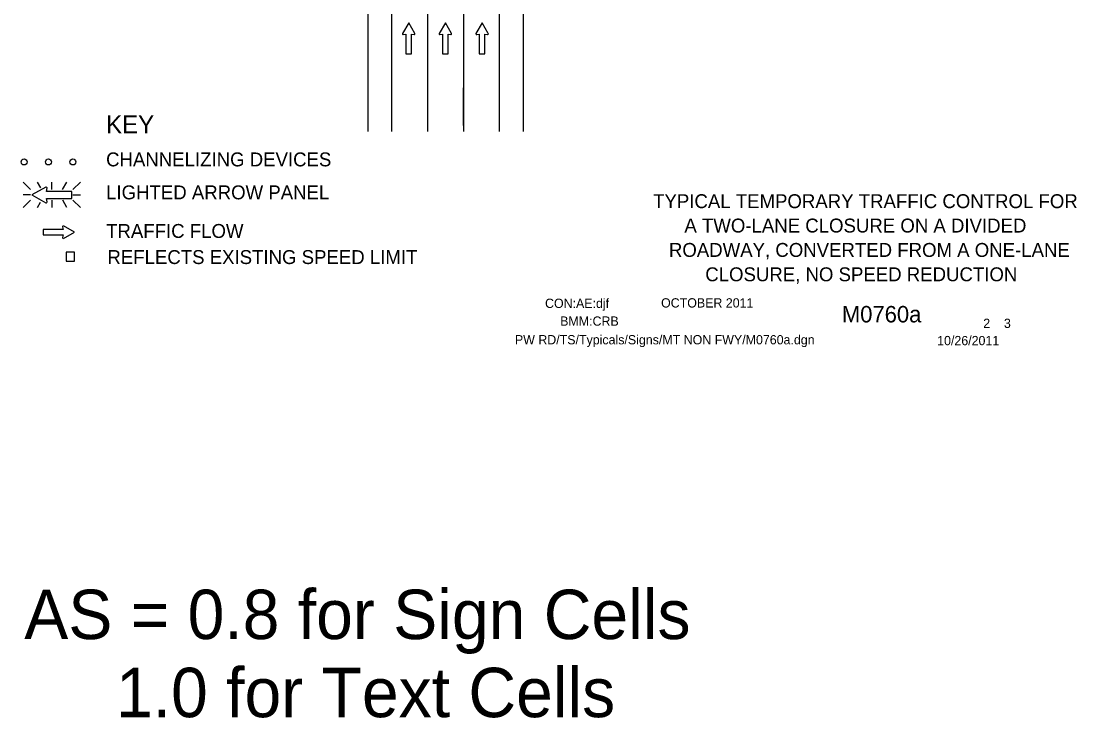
# Model space of a CAD drawing. Extents: x 16735 to 19504, y 6970 to 8243.
# Drawn here: x 17769 to 18475, y 6970 to 7436 of the extents above; entities that cross this region are included whole.
import ezdxf

# ---------------------------------------------------------------- set-up
doc = ezdxf.new("R2010")
doc.units = 0
for name, color, linetype in [('ALI_LEGAL_EX', 7, 'Continuous'), ('BORDER', 7, 'Continuous'), ('BORDER_SIGNAL_WO', 7, 'Continuous'), ('MT_SCRATCH_LEVEL_E', 7, 'Continuous'), ('PAVT_EDGE_EX', 7, 'Continuous'), ('TRAFFIC_SIGNS_PR', 7, 'Continuous'), ('TYPICAL_TEXT_DIMEN_EX', 7, 'Continuous')]:
    doc.layers.add(name, color=color, linetype=linetype)

msp = doc.modelspace()

# ---------------------------------------------------------------- linework, layer by layer
at = {"layer": 'ALI_LEGAL_EX'}
for p, q in [((18041.08, 8191.4), (18041.08, 7362.22)), ((18065.08, 8191.4), (18065.08, 7362.22)), ((18065.08, 8191.4), (18065.08, 7362.22))]:
    msp.add_line(p, q, dxfattribs=at)
for points in [[(18041.08, 7391.4), (18041.08, 7366.4)], [(18065.08, 7366.4), (18065.08, 7391.4)], [(18065.08, 7391.4), (18065.08, 7366.4)]]:
    msp.add_lwpolyline(points, dxfattribs=at)
at = {"layer": 'MT_SCRATCH_LEVEL_E'}
for p, q in [((18028.52, 7435.04), (18024.41, 7427.8)), ((18028.52, 7435.04), (18024.41, 7427.8)), ((18032.66, 7427.8), (18028.52, 7435.04)), ((18032.66, 7427.8), (18028.52, 7435.04)), ((18053.05, 7435.04), (18048.94, 7427.8)), ((18053.05, 7435.04), (18048.94, 7427.8)), ((18057.19, 7427.8), (18053.05, 7435.04)), ((18057.19, 7427.8), (18053.05, 7435.04)), ((18077.6, 7435.04), (18073.49, 7427.8)), ((18077.6, 7435.04), (18073.49, 7427.8)), ((18081.75, 7427.8), (18077.6, 7435.04)), ((18081.75, 7427.8), (18077.6, 7435.04)), ((18024.89, 7427.11), (18026.67, 7427.43)), ((18024.89, 7427.11), (18026.67, 7427.43)), ((18026.67, 7427.43), (18026.67, 7414.17)), ((18026.67, 7427.43), (18026.67, 7414.17)), ((18030.41, 7414.17), (18030.41, 7427.43)), ((18030.41, 7427.43), (18032.18, 7427.11)), ((18030.41, 7414.17), (18030.41, 7427.43)), ((18030.41, 7427.43), (18032.18, 7427.11)), ((18049.42, 7427.11), (18051.19, 7427.43)), ((18049.42, 7427.11), (18051.19, 7427.43)), ((18051.19, 7427.43), (18051.19, 7414.17)), ((18051.19, 7427.43), (18051.19, 7414.17)), ((18054.94, 7414.17), (18054.94, 7427.43)), ((18054.94, 7427.43), (18056.71, 7427.11)), ((18054.94, 7414.17), (18054.94, 7427.43)), ((18054.94, 7427.43), (18056.71, 7427.11)), ((18073.98, 7427.11), (18075.75, 7427.43)), ((18073.98, 7427.11), (18075.75, 7427.43)), ((18075.75, 7427.43), (18075.75, 7414.17)), ((18075.75, 7427.43), (18075.75, 7414.17)), ((18079.49, 7414.17), (18079.49, 7427.43)), ((18079.49, 7427.43), (18081.27, 7427.11)), ((18079.49, 7414.17), (18079.49, 7427.43)), ((18079.49, 7427.43), (18081.27, 7427.11)), ((18026.67, 7414.17), (18030.41, 7414.17)), ((18026.67, 7414.17), (18030.41, 7414.17)), ((18051.19, 7414.17), (18054.94, 7414.17)), ((18051.19, 7414.17), (18054.94, 7414.17)), ((18075.75, 7414.17), (18079.49, 7414.17)), ((18075.75, 7414.17), (18079.49, 7414.17)), ((17797.33, 7296.85), (17784.07, 7296.85)), ((17784.07, 7296.85), (17784.07, 7293.11)), ((17797.33, 7296.85), (17784.07, 7296.85)), ((17784.07, 7296.85), (17784.07, 7293.11)), ((17797.02, 7298.63), (17797.33, 7296.85)), ((17797.02, 7298.63), (17797.33, 7296.85)), ((17804.94, 7295), (17797.7, 7299.11)), ((17804.94, 7295), (17797.7, 7299.11)), ((17797.7, 7290.85), (17804.94, 7295)), ((17797.7, 7290.85), (17804.94, 7295)), ((17784.07, 7293.11), (17797.33, 7293.11)), ((17784.07, 7293.11), (17797.33, 7293.11)), ((17797.33, 7293.11), (17797.02, 7291.33)), ((17797.33, 7293.11), (17797.02, 7291.33))]:
    msp.add_line(p, q, dxfattribs=at)
for centre, start, end in [((18024.81, 7427.57), 150.42484, 279.96381), ((18024.81, 7427.57), 150.42484, 279.96381), ((18032.25, 7427.58), 260.03619, 29.77312), ((18032.25, 7427.58), 260.03619, 29.77312), ((18049.34, 7427.57), 150.42484, 279.96381), ((18049.34, 7427.57), 150.42484, 279.96381), ((18056.78, 7427.58), 260.03619, 29.77312), ((18056.78, 7427.58), 260.03619, 29.77312), ((18073.9, 7427.57), 150.42484, 279.96381), ((18073.9, 7427.57), 150.42484, 279.96381), ((18081.34, 7427.58), 260.03619, 29.77312), ((18081.34, 7427.58), 260.03619, 29.77312), ((17797.48, 7298.7), 60.42484, 189.96381), ((17797.48, 7298.7), 60.42484, 189.96381), ((17797.48, 7291.26), 170.03619, 299.77312), ((17797.48, 7291.26), 170.03619, 299.77312)]:
    msp.add_arc(centre, 0.463, start, end, dxfattribs=at)
at = {"layer": 'PAVT_EDGE_EX'}
for p, q in [((18001.08, 8191.4), (18001.08, 7362.22)), ((18017.08, 8191.4), (18017.08, 7362.22)), ((18017.08, 8191.4), (18017.08, 7362.22)), ((18089.08, 8191.4), (18089.08, 7362.22)), ((18105.08, 8191.4), (18105.08, 7362.22))]:
    msp.add_line(p, q, dxfattribs=at)
at = {"layer": 'TRAFFIC_SIGNS_PR'}
for p, q in [((17770.75, 7328.38), (17775.69, 7323.45)), ((17782.51, 7324.56), (17780.31, 7328.39)), ((17789.83, 7323.45), (17789.83, 7328.39)), ((17797.07, 7323.45), (17799.92, 7328.39)), ((17803.98, 7323.45), (17808.92, 7328.39)), ((17775.69, 7319.9), (17770.75, 7319.9)), ((17770.75, 7311.41), (17775.69, 7316.34)), ((17780.26, 7311.4), (17782.38, 7315.07)), ((17789.83, 7316.34), (17789.83, 7311.4)), ((17799.96, 7311.4), (17797.11, 7316.34)), ((17803.98, 7319.9), (17808.92, 7319.9)), ((17803.98, 7316.34), (17808.92, 7311.4))]:
    msp.add_line(p, q, dxfattribs=at)
for points in [[(17785.76, 7325.17), (17776.47, 7319.9), (17785.76, 7314.57)], [(17786.64, 7315.2), (17786.24, 7317.47), (17803.25, 7317.47), (17803.25, 7322.27), (17786.24, 7322.27), (17786.64, 7324.55)]]:
    msp.add_lwpolyline(points, dxfattribs=at)
msp.add_lwpolyline([(17799.53, 7275.51), (17805.12, 7275.51), (17805.12, 7281.68), (17799.53, 7281.68)], close=True, dxfattribs=at)
for centre in [(17771.31, 7341.93), (17787.61, 7341.93), (17803.91, 7341.93)]:
    msp.add_circle(centre, 2, dxfattribs=at)
for centre, radius, start, end in [((17786.05, 7324.65), 0.598, 350.73078, 118.89165), ((17786.05, 7315.1), 0.597, 241.48329, 9.95933)]:
    msp.add_arc(centre, radius, start, end, dxfattribs=at)

# ---------------------------------------------------------------- texts
at = {"layer": 'BORDER'}
for s, p in [('TYPICAL TEMPORARY TRAFFIC CONTROL FOR', (18191.96, 7311.05)), ('A TWO-LANE CLOSURE ON A DIVIDED', (18212.89, 7294.75)), ('ROADWAY, CONVERTED FROM A ONE-LANE', (18202.54, 7278.45)), ('CLOSURE, NO SPEED REDUCTION', (18226.85, 7262.15))]:
    msp.add_text(s, height=9.3, dxfattribs=at).set_placement(p)
at = {"layer": 'BORDER_SIGNAL_WO'}
for s, height, p in [('CON:AE:djf', 6.2, (18119.69, 7244.31)), ('    OCTOBER 2011    ', 6.2, (18188.08, 7244.59)), ('    M0760a   ', 11, (18301.86, 7234.63)), ('BMM:CRB   ', 6.2, (18129.81, 7232.42)), (' 2    3 ', 6.2, (18410.45, 7230.95)), ('PW RD/TS/Typicals/Signs/MT NON FWY/M0760a.dgn    ', 6.2, (18099.55, 7219.96)), ('10/26/2011    ', 6.2, (18381.93, 7219.38)), ('AS = 0.8 for Sign Cells', 33.0301, (17771.41, 7022.87)), ('     1.0 for Text Cells', 33.0301, (17771.41, 6970.64))]:
    msp.add_text(s, height=height, dxfattribs=at).set_placement(p)
at = {"layer": 'TYPICAL_TEXT_DIMEN_EX'}
for s, height, p in [('KEY', 12, (17826.15, 7361.03)), ('CHANNELIZING DEVICES', 9.3, (17826.15, 7338.99)), ('LIGHTED ARROW PANEL', 9.3, (17826.15, 7316.94)), ('TRAFFIC FLOW', 9.3, (17826.15, 7291.14)), ('REFLECTS EXISTING SPEED LIMIT', 9.3, (17827.01, 7273.67))]:
    msp.add_text(s, height=height, dxfattribs=at).set_placement(p)

doc.saveas('drawing.dxf')
